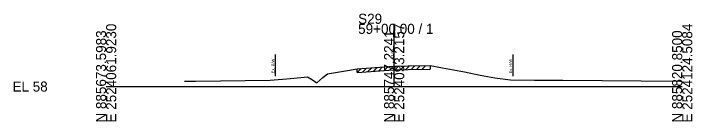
# Model space of a CAD drawing. Extents: x -26 to 163, y -10 to 4024.
# Drawn here: x -25.7 to 162.8, y -9.7 to 20.3 of the extents above; entities that cross this region are included whole.
import ezdxf

# ---------------------------------------------------------------- set-up
doc = ezdxf.new("R2010")
doc.units = 0
for name, color, linetype in [('RD_GPK_XS_Cell', 7, 'Continuous'), ('RD_XS_ExGround', 7, 'Continuous'), ('RD_XS_ExPaveRet', 7, 'Continuous'), ('RD_XS_ExRW', 7, 'Continuous'), ('RD_XS_TX_Elev_EX', 7, 'Continuous')]:
    doc.layers.add(name, color=color, linetype=linetype)

msp = doc.modelspace()

# ---------------------------------------------------------------- linework, layer by layer
at = {"layer": 'RD_GPK_XS_Cell'}
for p, q in [((80, 0), (80, 17.44)), ((0, 0), (80, 0)), ((80, 0), (160, 0))]:
    msp.add_line(p, q, dxfattribs=at)
at = {"layer": 'RD_XS_ExGround'}
for p, q in [((73.48, 5.2), (79.77, 5.66)), ((79.77, 5.66), (83.92, 5.72)), ((83.92, 5.72), (89.99, 5.81)), ((89.99, 5.81), (93.39, 5.2)), ((61.46, 3.55), (67.01, 4.45)), ((67.01, 4.45), (69.73, 4.92)), ((69.73, 4.92), (73.48, 5.2)), ((93.39, 5.2), (99.55, 4.11)), ((99.55, 4.11), (103.87, 3.21)), ((45.55, 1.8), (51.2, 2.26)), ((51.2, 2.26), (55.98, 2.74)), ((55.98, 2.74), (57.35, 1.9)), ((57.35, 1.9), (58.57, 1.06)), ((58.57, 1.06), (60.22, 2.54)), ((60.22, 2.54), (61.46, 3.55)), ((103.87, 3.21), (107.98, 2.43)), ((107.98, 2.43), (112.31, 1.89)), ((112.31, 1.89), (119, 1.78)), ((21.78, 1.49), (24.8, 1.53)), ((24.8, 1.53), (45.55, 1.8)), ((119, 1.78), (126.89, 1.73)), ((126.89, 1.73), (159.56, 1.49)), ((159.56, 1.49), (160, 1.49))]:
    msp.add_line(p, q, dxfattribs=at)
at = {"layer": 'RD_XS_ExPaveRet'}
for p, q in [((78.73, 4.58), (79.8, 5.66)), ((80.23, 4.66), (81.24, 5.68)), ((81.73, 4.69), (82.74, 5.7)), ((83.23, 4.71), (84.24, 5.72)), ((84.73, 4.73), (85.74, 5.75)), ((86.23, 4.75), (87.24, 5.77)), ((87.73, 4.78), (88.74, 5.79)), ((89.99, 5.81), (89.99, 4.81)), ((69.73, 3.92), (70.8, 5)), ((69.73, 3.92), (69.73, 4.92)), ((69.73, 3.92), (73.48, 4.2)), ((71.23, 4.03), (72.3, 5.11)), ((72.73, 4.14), (73.8, 5.22)), ((73.48, 4.2), (79.77, 4.66)), ((74.23, 4.25), (75.3, 5.33)), ((75.73, 4.36), (76.8, 5.44)), ((77.23, 4.47), (78.3, 5.55)), ((79.77, 4.66), (83.92, 4.72)), ((83.92, 4.72), (89.99, 4.81))]:
    msp.add_line(p, q, dxfattribs=at)
at = {"layer": 'RD_XS_ExRW'}
for p, q in [((47, 8.92), (47, 2.92)), ((113, 8.88), (113, 2.88))]:
    msp.add_line(p, q, dxfattribs=at)

# ---------------------------------------------------------------- texts
at = {"layer": 'RD_GPK_XS_Cell'}
for s, p in [('S29', (70, 17.44)), ('59+00.00 / 1', (70, 14.64)), ('EL 58', (-26, -1.4))]:
    msp.add_text(s, height=2.8, dxfattribs=at).set_placement(p)
for s, p in [('E 2524061.9230', (2.8, -10)), ('E 2524093.2157', (82.8, -10)), ('E 2524124.5084', (162.8, -10)), ('N 885673.5983', (0, -10)), ('N 885747.2241', (80, -10)), ('N 885820.8500', (160, -10))]:
    msp.add_text(s, height=2.8, rotation=90, dxfattribs=at).set_placement(p)
at = {"layer": 'RD_XS_ExRW'}
for p in [(46.75, 3.7), (112.75, 3.66)]:
    msp.add_text('Ex. R/W ', height=0.8, rotation=90, dxfattribs=at).set_placement(p)
at = {"layer": 'RD_XS_TX_Elev_EX'}
msp.add_text('63.66', height=0.8, rotation=90, dxfattribs=at).set_placement((79.9, 7.66))

doc.saveas('drawing.dxf')
